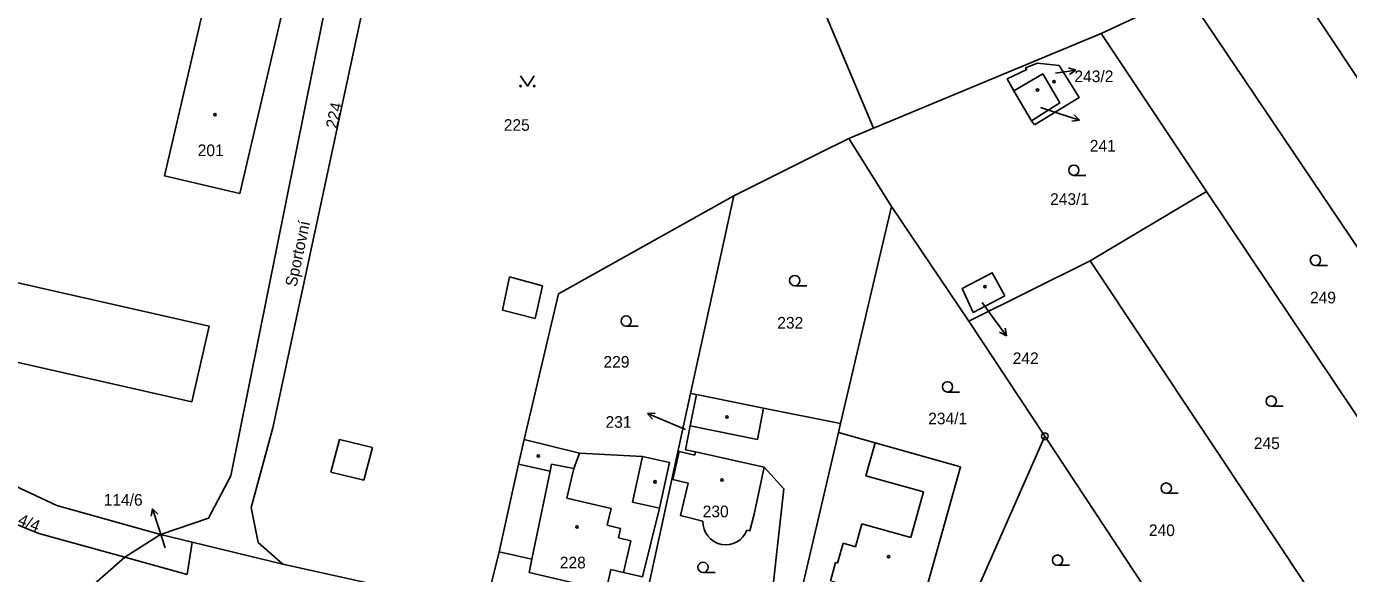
# Model space of a CAD drawing. Extents: x -504988 to -494607, y -1123820 to -1114018.
# Drawn here: x -497189.2 to -496996.2, y -1120209.1 to -1120129.3 of the extents above; entities that cross this region are included whole.
import ezdxf

# ---------------------------------------------------------------- set-up
doc = ezdxf.new("R2010")
doc.units = 0
for name, color, linetype in [('Hranice parcel', 7, 'Continuous'), ('Parcelní čísla', 7, 'Continuous'), ('Pop  PČ popisy', 7, 'Continuous'), ('Vnitřní kresba', 7, 'Continuous'), ('Značky bodu BP', 7, 'Continuous'), ('Značky budov', 7, 'Continuous'), ('Značky kultur', 7, 'Continuous')]:
    doc.layers.add(name, color=color, linetype=linetype)

msp = doc.modelspace()

# ---------------------------------------------------------------- linework, layer by layer
at = {"layer": 'Hranice parcel'}
for p, q in [((-497065.57, -1120144.14), (-497086.56, -1120094.23)), ((-496969.48, -1120175.1), (-497007.06, -1120118.48)), ((-497032.31, -1120130.33), (-497019.85, -1120124.5)), ((-496980.54, -1120182.87), (-497019.85, -1120124.5)), ((-497065.57, -1120144.14), (-497032.31, -1120130.33)), ((-497032.31, -1120130.33), (-497016.94, -1120153.36)), ((-497045.08, -1120138.67), (-497046.04, -1120136.91)), ((-497045.08, -1120138.67), (-497042.47, -1120143.05)), ((-497042.03, -1120143.65), (-497042.47, -1120143.05)), ((-497069.17, -1120145.62), (-497065.57, -1120144.14)), ((-497062.92, -1120155.56), (-497069.17, -1120145.62)), ((-497092.25, -1120182.81), (-497085.95, -1120154.01)), ((-497016.94, -1120153.36), (-497033.9, -1120163.46)), ((-496982.41, -1120204.92), (-497016.94, -1120153.36)), ((-497051.63, -1120172.28), (-497062.92, -1120155.56)), ((-497033.9, -1120163.46), (-497051.63, -1120172.28)), ((-496998.2, -1120217.1), (-497033.9, -1120163.46)), ((-497051.63, -1120172.28), (-497040.54, -1120189.06)), ((-497099.84, -1120217.48), (-497092.25, -1120182.81)), ((-497091.39, -1120182.98), (-497092.25, -1120182.81)), ((-497070.67, -1120188.52), (-497070.36, -1120187.2)), ((-497078.5, -1120221.85), (-497070.67, -1120188.52)), ((-497058.39, -1120229.47), (-497040.54, -1120189.06)), ((-497040.54, -1120189.06), (-497020.22, -1120219.8)), ((-497174.87, -1120206.72), (-497169.64, -1120203.41)), ((-497165.03, -1120204.53), (-497169.64, -1120203.41)), ((-497165.03, -1120204.53), (-497165.76, -1120209.25)), ((-497151.8, -1120207.74), (-497165.03, -1120204.53)), ((-497174.87, -1120206.72), (-497165.76, -1120209.25)), ((-497121.92, -1120212.76), (-497120.2, -1120205.93))]:
    msp.add_line(p, q, dxfattribs=at)
for points in [[(-497151.8, -1120207.74), (-497155.41, -1120204.55), (-497156.41, -1120199.47), (-497153.26, -1120187.82), (-497134.27, -1120099.43), (-497132.18, -1120096.08), (-497128.54, -1120094.95), (-497092.31, -1120103.83), (-497091.11, -1120099.77), (-497127.35, -1120090.65), (-497129.87, -1120089.52), (-497130.92, -1120086.64), (-497142.05, -1120084.42), (-497143.48, -1120089.09), (-497140.74, -1120091.07), (-497139.26, -1120095.09), (-497159.4, -1120194.83), (-497162.63, -1120201), (-497169.64, -1120203.41)], [(-497146.84, -1120105.6), (-497150.06, -1120104.85), (-497152.43, -1120104.3), (-497157.86, -1120103.03), (-497169.06, -1120151.08), (-497158.04, -1120153.65), (-497146.84, -1120105.6)], [(-497046.04, -1120136.91), (-497043.17, -1120135.55), (-497043.36, -1120135.3), (-497041.62, -1120134.62), (-497038.45, -1120134.99), (-497035.54, -1120139.67), (-497042.03, -1120143.65)], [(-497042.47, -1120143.05), (-497038.36, -1120140.45), (-497040.84, -1120136.22), (-497045.08, -1120138.67)], [(-497085.95, -1120154.01), (-497073.68, -1120147.87), (-497069.17, -1120145.62)], [(-497116.57, -1120189.55), (-497111.52, -1120168.28), (-497085.95, -1120154.01)], [(-497070.36, -1120187.2), (-497064.53, -1120162.37), (-497062.92, -1120155.56)], [(-497213.51, -1120161.48), (-497216.01, -1120172.5), (-497165.05, -1120184.03), (-497162.56, -1120173), (-497213.51, -1120161.48)], [(-497046.39, -1120168.57), (-497048.22, -1120165.21), (-497052.6, -1120167.49), (-497051.01, -1120171), (-497046.39, -1120168.57)], [(-497091.39, -1120182.98), (-497092.3, -1120187.54), (-497093, -1120191.03), (-497091.55, -1120191.35), (-497091.66, -1120191.8), (-497093.9, -1120191.27), (-497094.87, -1120195.35), (-497092.62, -1120195.89), (-497093.74, -1120200.6), (-497090.45, -1120201.45)], [(-497070.36, -1120187.2), (-497081.59, -1120184.95), (-497091.39, -1120182.98)], [(-497120.2, -1120205.93), (-497117.36, -1120193.14), (-497116.57, -1120189.55)], [(-497120.2, -1120205.93), (-497115.41, -1120206.97), (-497115.81, -1120208.93), (-497104.6, -1120211.56), (-497103.88, -1120208.5), (-497102.06, -1120208.93), (-497099.3, -1120209.57), (-497096.78, -1120199.54), (-497095.32, -1120192.9), (-497099.28, -1120192.03), (-497108.46, -1120191.52), (-497116.57, -1120189.55)], [(-497074.48, -1120223.29), (-497071.58, -1120210.26), (-497069.75, -1120210.77), (-497070.71, -1120214.19), (-497065.65, -1120215.79), (-497065.89, -1120216.65), (-497059.82, -1120218.35), (-497052.87, -1120193.5), (-497065.32, -1120190.02), (-497070.67, -1120188.52)], [(-497169.64, -1120203.41), (-497184.78, -1120199.15), (-497199.38, -1120192.34)], [(-497084.03, -1120202.76), (-497083.59, -1120202.85), (-497082.96, -1120200.42), (-497081.53, -1120193.57), (-497078.64, -1120196.72), (-497081.06, -1120218.64), (-497083.15, -1120220.9)], [(-497202.72, -1120196.14), (-497191.23, -1120201.67), (-497187.4, -1120203.24), (-497174.87, -1120206.72)], [(-497090.45, -1120201.45), (-497090.42, -1120202.03), (-497090.29, -1120202.59), (-497090.07, -1120203.12), (-497089.76, -1120203.6), (-497089.37, -1120204.03), (-497088.91, -1120204.38), (-497088.4, -1120204.64), (-497088.3, -1120204.68), (-497087.74, -1120204.84), (-497087.17, -1120204.89), (-497086.59, -1120204.85), (-497086.04, -1120204.71), (-497085.51, -1120204.47), (-497085.03, -1120204.15), (-497084.62, -1120203.75), (-497084.28, -1120203.28), (-497084.03, -1120202.76)], [(-497206.76, -1120232.05), (-497192.01, -1120221.83), (-497174.87, -1120206.72)], [(-497121.92, -1120212.76), (-497122.35, -1120214.22), (-497151.8, -1120207.74)]]:
    msp.add_lwpolyline(points, dxfattribs=at)
at = {"layer": 'Pop  PČ popisy'}
for p, q in [((-497036.02, -1120135.66), (-497037.08, -1120135.31)), ((-497038.99, -1120136.08), (-497036.02, -1120135.66)), ((-497036.02, -1120135.66), (-497036.94, -1120136.3)), ((-497041.19, -1120141.1), (-497038.33, -1120142.02)), ((-497038.33, -1120142.02), (-497035.48, -1120142.95)), ((-497035.48, -1120142.95), (-497036.58, -1120143.11)), ((-497035.48, -1120142.95), (-497036.27, -1120142.16)), ((-497049.69, -1120169.55), (-497047.92, -1120171.97)), ((-497047.92, -1120171.97), (-497046.16, -1120174.4)), ((-497046.16, -1120174.4), (-497047.15, -1120173.88)), ((-497046.16, -1120174.4), (-497046.34, -1120173.29)), ((-497098.54, -1120185.74), (-497097.42, -1120185.67)), ((-497095.78, -1120186.91), (-497098.54, -1120185.74)), ((-497098.54, -1120185.74), (-497097.82, -1120186.59)), ((-497093.02, -1120188.07), (-497095.78, -1120186.91)), ((-497170.83, -1120199.63), (-497170.99, -1120200.73)), ((-497169.9, -1120202.48), (-497170.83, -1120199.63)), ((-497170.83, -1120199.63), (-497170.04, -1120200.42)), ((-497168.98, -1120205.34), (-497169.9, -1120202.48))]:
    msp.add_line(p, q, dxfattribs=at)
at = {"layer": 'Vnitřní kresba'}
for p, q in [((-497119.72, -1120170.67), (-497118.67, -1120165.83)), ((-497118.67, -1120165.83), (-497113.9, -1120167.11)), ((-497113.9, -1120167.11), (-497114.93, -1120171.87)), ((-497114.93, -1120171.87), (-497119.72, -1120170.67)), ((-497081.59, -1120184.95), (-497082.5, -1120189.51)), ((-497082.5, -1120189.51), (-497092.3, -1120187.54)), ((-497144.79, -1120194.3), (-497143.51, -1120189.55)), ((-497143.51, -1120189.55), (-497138.7, -1120190.69)), ((-497138.7, -1120190.69), (-497139.94, -1120195.47)), ((-497091.55, -1120191.35), (-497081.53, -1120193.57)), ((-497066.66, -1120194.82), (-497065.32, -1120190.02)), ((-497112.75, -1120194.16), (-497117.36, -1120193.14)), ((-497112.75, -1120194.16), (-497112.54, -1120193.12)), ((-497112.54, -1120193.12), (-497109.28, -1120193.74)), ((-497108.46, -1120191.52), (-497109.28, -1120193.74)), ((-497100.74, -1120198.67), (-497099.28, -1120192.03)), ((-497139.94, -1120195.47), (-497144.79, -1120194.3)), ((-497115.41, -1120206.97), (-497112.75, -1120194.16)), ((-497109.28, -1120193.74), (-497110.3, -1120198.07)), ((-497058.26, -1120197.17), (-497066.66, -1120194.82)), ((-497060.12, -1120203.84), (-497058.26, -1120197.17)), ((-497110.3, -1120198.07), (-497103.87, -1120199.58)), ((-497096.78, -1120199.54), (-497100.74, -1120198.67)), ((-497103.87, -1120199.58), (-497104.45, -1120202.05)), ((-497104.45, -1120202.05), (-497102.48, -1120202.51)), ((-497102.48, -1120202.51), (-497102.8, -1120203.9)), ((-497068.18, -1120205.18), (-497067.25, -1120201.85)), ((-497067.25, -1120201.85), (-497060.12, -1120203.84)), ((-497102.8, -1120203.9), (-497100.98, -1120204.33)), ((-497100.98, -1120204.33), (-497102.06, -1120208.93)), ((-497070.8, -1120207.57), (-497069.99, -1120204.67)), ((-497069.99, -1120204.67), (-497068.18, -1120205.18)), ((-497071.84, -1120210.19), (-497071.09, -1120207.49)), ((-497071.09, -1120207.49), (-497070.8, -1120207.57))]:
    msp.add_line(p, q, dxfattribs=at)
at = {"layer": 'Značky bodu BP'}
for radius in [0.5, 0.0303]:
    msp.add_circle((-497040.54, -1120189.06), radius, dxfattribs=at)
at = {"layer": 'Značky budov'}
for centre in [(-497039.19, -1120137.33), (-497041.61, -1120138.56), (-497161.69, -1120142.15), (-497049.29, -1120167.26), (-497086.95, -1120186.24), (-497114.5, -1120191.94), (-497087.69, -1120195.44), (-497097.45, -1120195.71), (-497108.83, -1120202.29), (-497063.36, -1120206.62)]:
    msp.add_circle(centre, 0.175, dxfattribs=at)
at = {"layer": 'Značky kultur'}
for p, q in [((-497036.31, -1120151.01), (-497034.56, -1120151.01)), ((-497001.04, -1120164.14), (-496999.29, -1120164.14)), ((-497077.06, -1120167.11), (-497075.31, -1120167.11)), ((-497101.66, -1120173), (-497099.91, -1120173)), ((-497054.75, -1120182.61), (-497053, -1120182.61)), ((-497007.49, -1120184.68), (-497005.74, -1120184.68)), ((-497022.81, -1120197.37), (-497021.06, -1120197.37)), ((-497038.68, -1120207.88), (-497036.93, -1120207.88)), ((-497090.44, -1120208.93), (-497088.69, -1120208.93))]:
    msp.add_line(p, q, dxfattribs=at)
msp.add_lwpolyline([(-497117.08, -1120136.49), (-497116.08, -1120137.99), (-497115.08, -1120136.49)], dxfattribs=at)
for centre, radius in [((-497117.08, -1120137.99), 0.1), ((-497115.08, -1120137.99), 0.1), ((-497036.31, -1120150.26), 0.75), ((-497001.04, -1120163.39), 0.75), ((-497077.06, -1120166.36), 0.75), ((-497101.66, -1120172.25), 0.75), ((-497054.75, -1120181.86), 0.75), ((-497007.49, -1120183.93), 0.75), ((-497022.81, -1120196.62), 0.75), ((-497038.68, -1120207.13), 0.75), ((-497090.44, -1120208.18), 0.75)]:
    msp.add_circle(centre, radius, dxfattribs=at)

# ---------------------------------------------------------------- texts
at = {"layer": 'Parcelní čísla'}
for s, p in [('243/2', (-497036.22, -1120137.41)), ('225', (-497119.53, -1120144.51)), ('201', (-497164.21, -1120148.2)), ('241', (-497033.98, -1120147.54)), ('243/1', (-497039.77, -1120155.32)), ('249', (-497001.83, -1120169.68)), ('232', (-497079.6, -1120173.36)), ('229', (-497104.97, -1120179.06)), ('242', (-497045.23, -1120178.53)), ('234/1', (-497057.57, -1120187.32)), ('231', (-497104.67, -1120187.83)), ('245', (-497010.03, -1120190.93)), ('114/6', (-497177.94, -1120199.19)), ('230', (-497090.49, -1120200.88)), ('240', (-497025.35, -1120203.62)), ('228', (-497111.35, -1120208.34))]:
    msp.add_text(s, height=1.7, dxfattribs=at).set_placement(p)
for s, rotation, p in [('224', 78, (-497143.88, -1120144.28)), ('114/4', 338, (-497192.93, -1120200.92))]:
    msp.add_text(s, height=1.7, rotation=rotation, dxfattribs=at).set_placement(p)
at = {"layer": 'Pop  PČ popisy'}
msp.add_text('Sportovní', height=1.7, rotation=78, dxfattribs=at).set_placement((-497149.8, -1120167.36))

doc.saveas('drawing.dxf')
